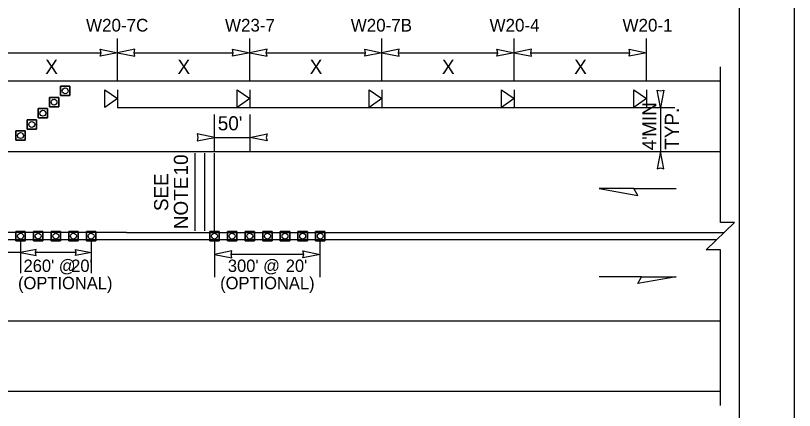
# Model space of a CAD drawing. Extents: x 99999.1 to 100095.7, y 99995 to 100010.7.
# Drawn here: x 100011.645 to 100016.062, y 100005.624 to 100007.863 of the extents above; entities that cross this region are included whole.
import ezdxf

# ---------------------------------------------------------------- set-up
doc = ezdxf.new("R2010")
doc.units = 0
for name, color, linetype in [('RD_ED_ShoulderPavedEdge', 7, 'Continuous'), ('RD_MK_LineDblYellowCenter', 7, 'Continuous'), ('RD_MK_LineEdgeWhite', 7, 'Continuous'), ('RD_MK_LineNoPass', 7, 'Continuous'), ('RD_MK_LineSkipCenter', 7, 'Continuous'), ('SH_GI_PlotLimits', 7, 'Continuous'), ('SH_GI_SheetBorder', 7, 'Continuous'), ('TR_SN_ConstructionSigns', 7, 'Continuous'), ('TR_WZ_PortableSignMountBlk-Org', 7, 'Continuous'), ('TR_WZ_TrafficCone', 7, 'Continuous'), ('TR_WZ_WorkZoneDetails', 7, 'Continuous'), ('TR_WZ_WorkZoneTextCurrent', 7, 'Continuous')]:
    doc.layers.add(name, color=color, linetype=linetype)

msp = doc.modelspace()

# ---------------------------------------------------------------- linework, layer by layer
at = {"layer": 'RD_ED_ShoulderPavedEdge'}
for p, q in [((100000.1076, 100007.4923), (100015.6424, 100007.4923)), ((100000.1076, 100005.7323), (100015.6424, 100005.7323))]:
    msp.add_line(p, q, dxfattribs=at)
at = {"layer": 'RD_MK_LineDblYellowCenter'}
for p, q in [((100012.2733, 100006.6323), (100015.6631, 100006.6323)), ((100012.2733, 100006.5923), (100015.6218, 100006.5923))]:
    msp.add_line(p, q, dxfattribs=at)
at = {"layer": 'RD_MK_LineEdgeWhite'}
for p, q in [((100000.1076, 100007.0923), (100015.6424, 100007.0923)), ((100000.1076, 100006.1323), (100015.6424, 100006.1323))]:
    msp.add_line(p, q, dxfattribs=at)
at = {"layer": 'RD_MK_LineNoPass'}
msp.add_line((100011.4733, 100006.5923), (100012.2733, 100006.5923), dxfattribs=at)
at = {"layer": 'RD_MK_LineSkipCenter'}
msp.add_lwpolyline([(100012.2733, 100006.6323), (100011.4733, 100006.6323)], dxfattribs=at)
at = {"layer": 'SH_GI_PlotLimits'}
msp.add_lwpolyline([(99999.0625, 99999.6875), (100016.0625, 99999.6875), (100016.0625, 100010.6875), (99999.0625, 100010.6875)], close=True, dxfattribs=at)
at = {"layer": 'SH_GI_SheetBorder'}
msp.add_line((100015.75, 100010.375), (100015.75, 100000), dxfattribs=at)
at = {"layer": 'TR_WZ_PortableSignMountBlk-Org'}
for p, q in [((100012.2233, 100007.4422), (100012.2233, 100007.3422)), ((100012.9733, 100007.4422), (100012.9733, 100007.3422)), ((100013.7233, 100007.4422), (100013.7233, 100007.3422)), ((100014.4733, 100007.4422), (100014.4733, 100007.3422)), ((100015.2233, 100007.4422), (100015.2233, 100007.3422))]:
    msp.add_line(p, q, dxfattribs=at)
for points in [[(100012.2233, 100007.3923), (100012.1515, 100007.3422), (100012.1515, 100007.4422)], [(100012.9733, 100007.3923), (100012.9015, 100007.3422), (100012.9015, 100007.4422)], [(100013.7233, 100007.3923), (100013.6515, 100007.3422), (100013.6515, 100007.4422)], [(100014.4733, 100007.3923), (100014.4015, 100007.3422), (100014.4015, 100007.4422)], [(100015.2233, 100007.3923), (100015.1515, 100007.3422), (100015.1515, 100007.4422)]]:
    msp.add_lwpolyline(points, close=True, dxfattribs=at)
at = {"layer": 'TR_WZ_TrafficCone'}
for points in [[(100011.9533, 100007.4623), (100011.9, 100007.4623), (100011.9, 100007.409), (100011.9533, 100007.409), (100011.9533, 100007.4623)], [(100011.9533, 100007.409), (100011.9, 100007.409), (100011.9, 100007.4623), (100011.9533, 100007.4623), (100011.9533, 100007.409)], [(100011.89, 100007.399), (100011.8367, 100007.399), (100011.8367, 100007.3457), (100011.89, 100007.3457), (100011.89, 100007.399)], [(100011.89, 100007.3457), (100011.8367, 100007.3457), (100011.8367, 100007.399), (100011.89, 100007.399), (100011.89, 100007.3457)], [(100011.8267, 100007.3357), (100011.7733, 100007.3357), (100011.7733, 100007.2823), (100011.8267, 100007.2823), (100011.8267, 100007.3357)], [(100011.8267, 100007.2823), (100011.7733, 100007.2823), (100011.7733, 100007.3357), (100011.8267, 100007.3357), (100011.8267, 100007.2823)], [(100011.7633, 100007.219), (100011.71, 100007.219), (100011.71, 100007.2723), (100011.7633, 100007.2723), (100011.7633, 100007.219)], [(100011.7633, 100007.2723), (100011.71, 100007.2723), (100011.71, 100007.219), (100011.7633, 100007.219), (100011.7633, 100007.2723)], [(100011.7, 100007.1557), (100011.6467, 100007.1557), (100011.6467, 100007.209), (100011.7, 100007.209), (100011.7, 100007.1557)], [(100011.7, 100007.209), (100011.6467, 100007.209), (100011.6467, 100007.1557), (100011.7, 100007.1557), (100011.7, 100007.209)], [(100011.7, 100006.639), (100011.6467, 100006.639), (100011.6467, 100006.5857), (100011.7, 100006.5857), (100011.7, 100006.639)], [(100011.7, 100006.5857), (100011.6467, 100006.5857), (100011.6467, 100006.639), (100011.7, 100006.639), (100011.7, 100006.5857)], [(100011.8, 100006.639), (100011.7467, 100006.639), (100011.7467, 100006.5857), (100011.8, 100006.5857), (100011.8, 100006.639)], [(100011.8, 100006.5857), (100011.7467, 100006.5857), (100011.7467, 100006.639), (100011.8, 100006.639), (100011.8, 100006.5857)], [(100011.9, 100006.639), (100011.8467, 100006.639), (100011.8467, 100006.5857), (100011.9, 100006.5857), (100011.9, 100006.639)], [(100011.9, 100006.5857), (100011.8467, 100006.5857), (100011.8467, 100006.639), (100011.9, 100006.639), (100011.9, 100006.5857)], [(100012, 100006.639), (100011.9467, 100006.639), (100011.9467, 100006.5857), (100012, 100006.5857), (100012, 100006.639)], [(100012, 100006.5857), (100011.9467, 100006.5857), (100011.9467, 100006.639), (100012, 100006.639), (100012, 100006.5857)], [(100012.1, 100006.639), (100012.0467, 100006.639), (100012.0467, 100006.5857), (100012.1, 100006.5857), (100012.1, 100006.639)], [(100012.1, 100006.5857), (100012.0467, 100006.5857), (100012.0467, 100006.639), (100012.1, 100006.639), (100012.1, 100006.5857)], [(100012.8, 100006.5857), (100012.7467, 100006.5857), (100012.7467, 100006.639), (100012.8, 100006.639), (100012.8, 100006.5857)], [(100012.8, 100006.639), (100012.7467, 100006.639), (100012.7467, 100006.5857), (100012.8, 100006.5857), (100012.8, 100006.639)], [(100012.9, 100006.5857), (100012.8467, 100006.5857), (100012.8467, 100006.639), (100012.9, 100006.639), (100012.9, 100006.5857)], [(100012.9, 100006.639), (100012.8467, 100006.639), (100012.8467, 100006.5857), (100012.9, 100006.5857), (100012.9, 100006.639)], [(100013, 100006.5857), (100012.9467, 100006.5857), (100012.9467, 100006.639), (100013, 100006.639), (100013, 100006.5857)], [(100013, 100006.639), (100012.9467, 100006.639), (100012.9467, 100006.5857), (100013, 100006.5857), (100013, 100006.639)], [(100013.1, 100006.5857), (100013.0467, 100006.5857), (100013.0467, 100006.639), (100013.1, 100006.639), (100013.1, 100006.5857)], [(100013.1, 100006.639), (100013.0467, 100006.639), (100013.0467, 100006.5857), (100013.1, 100006.5857), (100013.1, 100006.639)], [(100013.2, 100006.5857), (100013.1467, 100006.5857), (100013.1467, 100006.639), (100013.2, 100006.639), (100013.2, 100006.5857)], [(100013.2, 100006.639), (100013.1467, 100006.639), (100013.1467, 100006.5857), (100013.2, 100006.5857), (100013.2, 100006.639)], [(100013.3, 100006.5857), (100013.2467, 100006.5857), (100013.2467, 100006.639), (100013.3, 100006.639), (100013.3, 100006.5857)], [(100013.3, 100006.639), (100013.2467, 100006.639), (100013.2467, 100006.5857), (100013.3, 100006.5857), (100013.3, 100006.639)], [(100013.4, 100006.5857), (100013.3467, 100006.5857), (100013.3467, 100006.639), (100013.4, 100006.639), (100013.4, 100006.5857)], [(100013.4, 100006.639), (100013.3467, 100006.639), (100013.3467, 100006.5857), (100013.4, 100006.5857), (100013.4, 100006.639)]]:
    msp.add_lwpolyline(points, dxfattribs=at)
for centre in [(100011.9267, 100007.4357), (100011.8633, 100007.3723), (100011.8, 100007.309), (100011.7367, 100007.2457), (100011.6733, 100007.1823), (100011.6733, 100006.6123), (100011.7733, 100006.6123), (100011.8733, 100006.6123), (100011.9733, 100006.6123), (100012.0733, 100006.6123), (100012.7733, 100006.6123), (100012.8733, 100006.6123), (100012.9733, 100006.6123), (100013.0733, 100006.6123), (100013.1733, 100006.6123), (100013.2733, 100006.6123), (100013.3733, 100006.6123)]:
    msp.add_circle(centre, 0.0167, dxfattribs=at)
at = {"layer": 'TR_WZ_WorkZoneDetails'}
for p, q in [((100012.2233, 100007.4923), (100012.2233, 100007.7323)), ((100012.9733, 100007.4923), (100012.9733, 100007.7323)), ((100013.7233, 100007.4923), (100013.7233, 100007.7323)), ((100014.4733, 100007.4923), (100014.4733, 100007.7323)), ((100015.2233, 100007.4921), (100015.2233, 100007.7323)), ((100011.5671, 100007.6523), (100012.1296, 100007.6523)), ((100012.3171, 100007.6523), (100012.8796, 100007.6523)), ((100013.0671, 100007.6523), (100013.6296, 100007.6523)), ((100013.8171, 100007.6523), (100014.3796, 100007.6523)), ((100014.5671, 100007.6523), (100015.1296, 100007.6523)), ((100012.2233, 100007.3422), (100015.2233, 100007.3422)), ((100015.2233, 100007.3422), (100015.3833, 100007.3422)), ((100015.3033, 100007.3422), (100015.3033, 100007.0923)), ((100012.7733, 100007.0923), (100012.7733, 100007.3023)), ((100012.9733, 100007.3023), (100012.9733, 100007.0923)), ((100012.7733, 100007.1723), (100012.9733, 100007.1723)), ((100012.6628, 100006.6423), (100012.6628, 100007.0823)), ((100012.7185, 100006.6423), (100012.7185, 100007.0823)), ((100012.7733, 100006.6423), (100012.7733, 100007.0823)), ((100015.2233, 100007.0923), (100015.3833, 100007.0923)), ((100015.1513, 100006.8816), (100015.3924, 100006.8816)), ((100011.6733, 100006.5857), (100011.6733, 100006.4023)), ((100012.0733, 100006.5857), (100012.0733, 100006.4023)), ((100012.7733, 100006.589), (100012.7733, 100006.379)), ((100013.3733, 100006.379), (100013.3733, 100006.589)), ((100011.6733, 100006.5193), (100011.4933, 100006.5193)), ((100011.989, 100006.5193), (100011.7577, 100006.5193)), ((100013.2796, 100006.509), (100012.8671, 100006.509)), ((100015.1959, 100006.3816), (100014.9548, 100006.3816))]:
    msp.add_line(p, q, dxfattribs=at)
for points in [[(100012.2233, 100007.6523), (100012.1251, 100007.6331), (100012.1296, 100007.6523), (100012.1251, 100007.6716)], [(100012.2233, 100007.6523), (100012.3216, 100007.6331), (100012.3171, 100007.6523), (100012.3216, 100007.6716)], [(100012.9733, 100007.6523), (100012.8751, 100007.6331), (100012.8796, 100007.6523), (100012.8751, 100007.6716)], [(100012.9733, 100007.6523), (100013.0716, 100007.6331), (100013.0671, 100007.6523), (100013.0716, 100007.6716)], [(100013.7233, 100007.6523), (100013.6251, 100007.6331), (100013.6296, 100007.6523), (100013.6251, 100007.6716)], [(100013.7233, 100007.6523), (100013.8216, 100007.6331), (100013.8171, 100007.6523), (100013.8216, 100007.6716)], [(100014.4733, 100007.6523), (100014.3751, 100007.6331), (100014.3796, 100007.6523), (100014.3751, 100007.6716)], [(100014.4733, 100007.6523), (100014.5716, 100007.6331), (100014.5671, 100007.6523), (100014.5716, 100007.6716)], [(100015.2233, 100007.6523), (100015.1251, 100007.6331), (100015.1296, 100007.6523), (100015.1251, 100007.6716)], [(100015.3033, 100007.3422), (100015.2841, 100007.4405), (100015.3033, 100007.436), (100015.3226, 100007.4405)], [(100012.7733, 100007.1723), (100012.6751, 100007.1916), (100012.6796, 100007.1723), (100012.6751, 100007.1531)], [(100012.9733, 100007.1723), (100013.0716, 100007.1916), (100013.0671, 100007.1723), (100013.0716, 100007.1531)], [(100015.3033, 100007.0923), (100015.2841, 100006.9941), (100015.3033, 100006.9986), (100015.3226, 100006.9941)], [(100014.9548, 100006.8816), (100015.1736, 100006.843), (100015.1513, 100006.8816)], [(100011.6733, 100006.5193), (100011.7618, 100006.502), (100011.7577, 100006.5193), (100011.7618, 100006.5367)], [(100012.0733, 100006.5193), (100011.9849, 100006.502), (100011.989, 100006.5193), (100011.9849, 100006.5367)], [(100012.7733, 100006.509), (100012.8716, 100006.4897), (100012.8671, 100006.509), (100012.8716, 100006.5283)], [(100013.3733, 100006.509), (100013.2751, 100006.4897), (100013.2796, 100006.509), (100013.2751, 100006.5283)], [(100015.3924, 100006.3816), (100015.1736, 100006.343), (100015.1959, 100006.3816)]]:
    msp.add_lwpolyline(points, close=True, dxfattribs=at)
msp.add_lwpolyline([(100015.6424, 100005.6523), (100015.6424, 100006.5349), (100015.5624, 100006.5349), (100015.7225, 100006.6898), (100015.6424, 100006.6898), (100015.6424, 100007.5723)], dxfattribs=at)

# ---------------------------------------------------------------- texts
at = {"layer": 'TR_SN_ConstructionSigns'}
for s, p in [('W20-7C', (100012.0447, 100007.7723)), ('W23-7', (100012.8328, 100007.7723)), ('W20-7B', (100013.546, 100007.7723)), ('W20-4', (100014.3334, 100007.7723)), ('W20-1', (100015.0875, 100007.7723))]:
    msp.add_text(s, height=0.072, rotation=360, dxfattribs=at).set_placement(p)
at = {"layer": 'TR_WZ_WorkZoneDetails'}
for s, p in [('10', (100012.6228, 100006.9566)), ('SEE', (100012.5108, 100006.7544)), ('NOTE', (100012.6228, 100006.6518))]:
    msp.add_text(s, height=0.08, rotation=90, dxfattribs=at).set_placement(p)
at = {"layer": 'TR_WZ_WorkZoneTextCurrent'}
for s, height, p in [('X', 0.08, (100011.8136, 100007.5323)), ('X', 0.08, (100012.5636, 100007.5323)), ('X', 0.08, (100013.3136, 100007.5323)), ('X', 0.08, (100014.0636, 100007.5323)), ('X', 0.08, (100014.8136, 100007.5323)), ("50'", 0.08, (100012.7921, 100007.2123)), ("260' @", 0.07, (100011.6903, 100006.4093)), ("20'", 0.07, (100011.9604, 100006.4093)), ("300' @", 0.07, (100012.8491, 100006.4093)), ("20'", 0.07, (100013.1775, 100006.4093)), ('(OPTIONAL)', 0.07, (100011.659, 100006.3113)), ('(OPTIONAL)', 0.07, (100012.8053, 100006.3113))]:
    msp.add_text(s, height=height, dxfattribs=at).set_placement(p)
for s, p in [('MIN', (100015.2793, 100007.1754)), ('TYP.', (100015.4073, 100007.1026)), ("4'", (100015.2793, 100007.0989))]:
    msp.add_text(s, height=0.08, rotation=90, dxfattribs=at).set_placement(p)

doc.saveas('drawing.dxf')
